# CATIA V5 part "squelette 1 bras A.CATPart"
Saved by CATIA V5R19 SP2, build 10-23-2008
Part number: squelette bras A
Publications: "Plan de symétrie", "Axe 1", "Axe 2", "Axe 3", "Plan exter gauche", "Plan exter droit", "Plan inter droit", "Plan inter gauche", "Plan inter bas", "Plan exter bas", "Plan.7", "Longueur 1 2", "Longueur 2 3", "Plan xy"
Bounding box of the stored display mesh (mm): x -100 to 100, y 0 to 0, z 0 to 300
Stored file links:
  G:\EU_thinkMotion\CFAO_2010\MMS_groupe3\MMS_groupe3\A reprendre\mmugnier\Systeme_Cric_Y\Systeme_Cric_Y\squelette 1 bras A.CATPart
  C:\Users\matthieu\Documents\2 IFMA\2 projet THINKMOTION\système avec squelette\feuille de parametres.CATPart
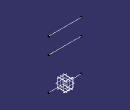
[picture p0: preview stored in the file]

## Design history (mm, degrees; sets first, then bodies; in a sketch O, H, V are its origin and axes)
Parameters
  `Longueur 1 2` = 250 mm
  `Longueur 2 3` = 50 mm
  `Largeur totale du mécanisme` = 35 mm
  `Epaisseur feuille` = 3 mm
Set1
  Line1 "Axe 1": type Normal, RefPoint {point type Coord, X 0, Y 0, Z 0}, RefSkin yz-plane, Start -100, End 100
  Line2 "Axe 2": type Normal, RefPoint {point type Coord, X 0, Y 0, Z 200}, RefSkin yz-plane, Start -100, End 100
  Line3 "Axe 3": type Normal, RefPoint {point type Coord, X 0, Y 0, Z 300 {= `Longueur 1 2` +`Longueur 2 3`}}, RefSkin yz-plane, Start -100, End 100
  Plane1 "Plan exter gauche": type Offset, RefPlane yz-plane, Offset 17.5 {= `Largeur totale du mécanisme` /2}
  Plane2 "Plan exter droit": type Offset, RefPlane yz-plane, Offset 17.5 {= `Largeur totale du mécanisme` /2}, reversed
  Plane3 "Plan inter droit": type Offset, RefPlane Plane2, Offset 3 {= `Epaisseur feuille`}
  Plane4 "Plan inter gauche": type Offset, RefPlane Plane1, Offset 3 {= `Epaisseur feuille`}, reversed
  Plane5 "Plan inter bas": type Offset, RefPlane zx-plane, Offset 17.5 {= `Largeur totale du mécanisme` /2}
  Plane6 "Plan exter bas": type Offset, RefPlane Plane5, Offset 3 {= `Epaisseur feuille`}
  Plane7: type Offset, RefPlane Plane5, Offset 35 {= `Largeur totale du mécanisme`}, reversed
Body1 (main body)
Relations
  Line2.Z = `Longueur 1 2` (deactivated)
